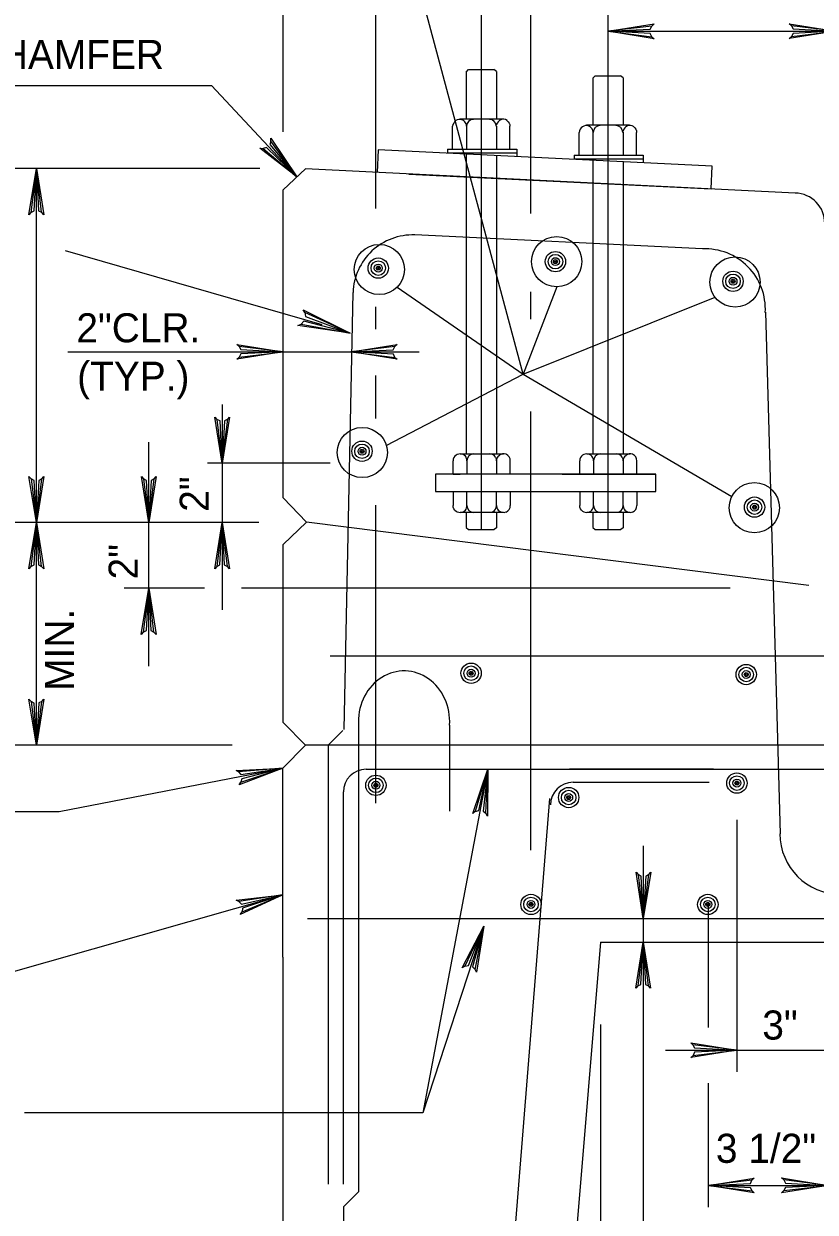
# Model space of a CAD drawing. Extents: x 642009 to 642864, y 298232 to 300014.
# Drawn here: x 642543.6 to 642625.2, y 298606.3 to 298729.1 of the extents above; entities that cross this region are included whole.
import ezdxf

# ---------------------------------------------------------------- set-up
doc = ezdxf.new("R2010")
doc.units = 0
for name, color, linetype in [('1', 7, 'Continuous'), ('10', 7, 'Continuous'), ('15', 7, 'Continuous'), ('2', 7, 'Continuous'), ('22', 7, 'Continuous'), ('3', 7, 'Continuous'), ('42', 7, 'Continuous')]:
    doc.layers.add(name, color=color, linetype=linetype)

msp = doc.modelspace()

# ---------------------------------------------------------------- linework, layer by layer
at = {"layer": '1'}
for p, q in [((642567.92, 298714.11), (642541.81, 298714.11)), ((642544.86, 298677.54), (642544.86, 298714.11)), ((642572.64, 298714.06), (642570.34, 298711.91)), ((642623.17, 298711.56), (642572.64, 298714.06)), ((642570.34, 298680.09), (642570.34, 298711.91)), ((642564.04, 298689.75), (642564.04, 298668.55)), ((642556.46, 298662.71), (642556.46, 298685.85)), ((642575.19, 298683.67), (642562.54, 298683.67)), ((642570.34, 298680.09), (642572.74, 298677.59)), ((642567.82, 298677.54), (642477.97, 298677.54)), ((642544.86, 298654.55), (642544.86, 298677.54)), ((642572.74, 298677.59), (642570.35, 298675.29)), ((642624.59, 298671.06), (642572.74, 298677.59)), ((642570.34, 298656.89), (642570.34, 298675.29)), ((642562.23, 298670.77), (642553.93, 298670.77)), ((642616.46, 298670.77), (642566.05, 298670.77)), ((642572.64, 298654.55), (642570.34, 298656.89)), ((642565.07, 298654.55), (642469.71, 298654.55)), ((642572.64, 298654.55), (642570.29, 298652.2)), ((642691.02, 298654.55), (642572.64, 298654.55)), ((642570.29, 298632.67), (642570.29, 298652.2)), ((642603.1, 298634.24), (642598.74, 298581.89)), ((642603.1, 298634.24), (642649.97, 298634.24)), ((642570.29, 298632.67), (642570.29, 298581.9))]:
    msp.add_line(p, q, dxfattribs=at)
for points in [[(642544.29, 298709.57), (642544.62, 298709.74), (642544.86, 298714.11), (642544.29, 298709.57), (642544.09, 298709.34), (642544.86, 298714.11), (642545.08, 298709.75), (642545.4, 298709.59), (642544.86, 298714.11), (642545.62, 298709.34), (642545.4, 298709.59)], [(642572.56, 298699.24), (642572.63, 298698.83), (642577.24, 298697.09), (642572.56, 298699.24), (642572.38, 298699.53), (642577.24, 298697.09), (642572.48, 298698.34), (642572.2, 298698.04), (642577.24, 298697.09), (642571.86, 298697.89), (642572.2, 298698.04)], [(642564.61, 298688.21), (642564.28, 298688.04), (642564.04, 298683.67), (642564.61, 298688.21), (642564.81, 298688.44), (642564.04, 298683.67), (642563.83, 298688.04), (642563.5, 298688.2), (642564.04, 298683.67), (642563.28, 298688.44), (642563.5, 298688.2)], [(642545.43, 298682.08), (642545.1, 298681.91), (642544.86, 298677.54), (642545.43, 298682.08), (642545.63, 298682.31), (642544.86, 298677.54), (642544.65, 298681.91), (642544.32, 298682.07), (642544.86, 298677.54), (642544.1, 298682.31), (642544.32, 298682.07)], [(642557.03, 298682.08), (642556.7, 298681.91), (642556.46, 298677.54), (642557.03, 298682.08), (642557.23, 298682.31), (642556.46, 298677.54), (642556.24, 298681.91), (642555.92, 298682.07), (642556.46, 298677.54), (642555.7, 298682.31), (642555.92, 298682.07)], [(642544.29, 298673), (642544.62, 298673.17), (642544.86, 298677.54), (642544.29, 298673), (642544.09, 298672.77), (642544.86, 298677.54), (642545.08, 298673.17), (642545.4, 298673.01), (642544.86, 298677.54), (642545.62, 298672.77), (642545.4, 298673.01)], [(642563.47, 298673), (642563.8, 298673.17), (642564.04, 298677.54), (642563.47, 298673), (642563.27, 298672.77), (642564.04, 298677.54), (642564.26, 298673.17), (642564.58, 298673.01), (642564.04, 298677.54), (642564.8, 298672.77), (642564.58, 298673.01)], [(642555.89, 298666.23), (642556.22, 298666.39), (642556.46, 298670.77), (642555.89, 298666.23), (642555.69, 298665.99), (642556.46, 298670.77), (642556.67, 298666.4), (642557, 298666.24), (642556.46, 298670.77), (642557.22, 298665.99), (642557, 298666.24)], [(642545.43, 298659.09), (642545.1, 298658.92), (642544.86, 298654.55), (642545.43, 298659.09), (642545.63, 298659.32), (642544.86, 298654.55), (642544.65, 298658.91), (642544.32, 298659.07), (642544.86, 298654.55), (642544.1, 298659.32), (642544.32, 298659.07)]]:
    msp.add_lwpolyline(points, dxfattribs=at)
msp.add_arc((642623.11, 298708.45), 3.12, 359.4063, 88.777, dxfattribs=at)
at = {"layer": '10'}
for p, q in [((642590.78, 298731.79), (642590.78, 298676.82)), ((642603.84, 298731.79), (642603.84, 298676.82))]:
    msp.add_line(p, q, dxfattribs=at)
at = {"layer": '15'}
for p, q in [((642613.6, 298705.8), (642583.91, 298707.25)), ((642577.52, 298701.3), (642576.58, 298656.18)), ((642621.66, 298645.42), (642620.13, 298699.29)), ((642626.89, 298663.74), (642575.19, 298663.74)), ((642578.11, 298657.16), (642578.11, 298608.46)), ((642574.98, 298654.55), (642576.48, 298656.08)), ((642587.51, 298656.64), (642587.51, 298647.75)), ((642574.98, 298654.55), (642574.98, 298609.24)), ((642578.89, 298652.09), (642674.18, 298652.09)), ((642614.73, 298652.09), (642599.89, 298652.09)), ((642600.26, 298650.73), (642614.3, 298650.73)), ((642576.55, 298609.24), (642576.55, 298649.74)), ((642592.98, 298588.14), (642597.85, 298649.06)), ((642572.84, 298636.68), (642678.54, 298636.68)), ((642578.11, 298608.46), (642576.55, 298606.9)), ((642576.55, 298606.9), (642576.55, 298588.15))]:
    msp.add_line(p, q, dxfattribs=at)
msp.add_lwpolyline([(642606.93, 298629.7), (642607.26, 298629.86), (642607.5, 298634.24), (642606.93, 298629.7), (642606.74, 298629.46), (642607.5, 298634.24), (642607.72, 298629.87), (642608.05, 298629.71), (642607.5, 298634.24), (642608.26, 298629.46), (642608.05, 298629.71)], dxfattribs=at)
for centre, radius, start, end in [((642583.7, 298701.09), 6.16, 88.0122, 178.0122), ((642613.88, 298699.59), 6.22, 356.8646, 92.5849), ((642578.89, 298649.74), 2.34, 90, 180), ((642600.26, 298648.39), 2.34, 90, 180), ((642627.85, 298645.42), 6.25, 180, 270)]:
    msp.add_arc(centre, radius, start, end, dxfattribs=at)
at = {"layer": '2'}
msp.add_ellipse((642582.81, 298657), major_axis=(0, 5.23), ratio=0.9, start_param=4.644026, end_param=7.865813, dxfattribs=at)
at = {"layer": '22'}
for p, q in [((642570.34, 298717.91), (642570.34, 298751.16)), ((642579.9, 298709.99), (642579.9, 298746)), ((642595.11, 298692.86), (642583, 298737.98)), ((642595.91, 298709.47), (642595.91, 298733.11)), ((642603.84, 298728.28), (642627.33, 298728.28)), ((642529.55, 298722.67), (642562.94, 298722.67)), ((642571.75, 298713.23), (642562.94, 298722.67)), ((642574.35, 298697.98), (642547.88, 298705.6)), ((642582.09, 298701.86), (642595.11, 298692.86)), ((642598.56, 298701.9), (642595.11, 298692.86)), ((642595.91, 298698.56), (642595.91, 298701.37)), ((642579.9, 298697.52), (642579.9, 298699.83)), ((642595.11, 298692.86), (642614.92, 298700.81)), ((642548.1, 298695.17), (642571.08, 298695.17)), ((642571.08, 298695.17), (642584.38, 298695.17)), ((642579.9, 298688.3), (642579.9, 298692.74)), ((642580.98, 298685.52), (642595.11, 298692.86)), ((642595.11, 298692.86), (642616.65, 298680.24)), ((642595.91, 298643.72), (642595.91, 298689.02)), ((642579.9, 298648.58), (642579.9, 298679.33)), ((642547.21, 298647.7), (642570.29, 298652.2)), ((642591.44, 298652.09), (642584.76, 298616.6)), ((642479.53, 298647.7), (642547.21, 298647.7)), ((642617.16, 298646.86), (642617.16, 298620.82)), ((642607.5, 298644.17), (642607.5, 298602.08)), ((642541.03, 298630.8), (642570.29, 298639.12)), ((642614.18, 298638.11), (642614.18, 298625.4)), ((642591.03, 298635.89), (642584.76, 298616.6)), ((642603.1, 298625.74), (642603.1, 298601.46)), ((642609.78, 298623.07), (642626.54, 298623.07)), ((642614.18, 298619.68), (642614.18, 298606.86)), ((642584.76, 298616.6), (642543.65, 298616.6)), ((642614.18, 298609.11), (642626.54, 298609.11))]:
    msp.add_line(p, q, dxfattribs=at)
for points in [[(642608.38, 298727.71), (642608.22, 298728.04), (642603.84, 298728.28), (642608.38, 298727.71), (642608.62, 298727.51), (642603.84, 298728.28), (642608.21, 298728.49), (642608.37, 298728.82), (642603.84, 298728.28), (642608.62, 298729.04), (642608.37, 298728.82)], [(642622.79, 298728.85), (642622.96, 298728.52), (642627.33, 298728.28), (642622.79, 298728.85), (642622.56, 298729.05), (642627.33, 298728.28), (642622.97, 298728.06), (642622.81, 298727.74), (642627.33, 298728.28), (642622.56, 298727.52), (642622.81, 298727.74)], [(642569.07, 298716.93), (642568.95, 298716.59), (642571.75, 298713.23), (642569.07, 298716.93), (642569.06, 298717.24), (642571.75, 298713.23), (642568.61, 298716.27), (642568.27, 298716.17), (642571.75, 298713.23), (642567.94, 298716.2), (642568.27, 298716.17)], [(642565.78, 298695.74), (642565.95, 298695.42), (642570.32, 298695.17), (642565.78, 298695.74), (642565.55, 298695.94), (642570.32, 298695.17), (642565.95, 298694.96), (642565.79, 298694.63), (642570.32, 298695.17), (642565.55, 298694.42), (642565.79, 298694.63)], [(642581.87, 298694.6), (642581.71, 298694.93), (642577.33, 298695.17), (642581.87, 298694.6), (642582.11, 298694.41), (642577.33, 298695.17), (642581.7, 298695.39), (642581.86, 298695.72), (642577.33, 298695.17), (642582.11, 298695.93), (642581.86, 298695.72)], [(642565.74, 298651.82), (642565.97, 298651.53), (642570.29, 298652.2), (642565.74, 298651.82), (642565.47, 298651.96), (642570.29, 298652.2), (642566.07, 298651.08), (642565.98, 298650.73), (642570.29, 298652.2), (642565.78, 298650.47), (642565.98, 298650.73)], [(642590.16, 298647.7), (642590.51, 298647.81), (642591.44, 298652.09), (642590.16, 298647.7), (642589.92, 298647.5), (642591.44, 298652.09), (642590.96, 298647.74), (642591.26, 298647.53), (642591.44, 298652.09), (642591.43, 298647.25), (642591.26, 298647.53)], [(642608.07, 298641.22), (642607.75, 298641.05), (642607.5, 298636.68), (642608.07, 298641.22), (642608.27, 298641.45), (642607.5, 298636.68), (642607.29, 298641.04), (642606.96, 298641.2), (642607.5, 298636.68), (642606.75, 298641.45), (642606.96, 298641.2)], [(642565.77, 298638.43), (642566.02, 298638.16), (642570.29, 298639.12), (642565.77, 298638.43), (642565.49, 298638.56), (642570.29, 298639.12), (642566.15, 298637.72), (642566.09, 298637.36), (642570.29, 298639.12), (642565.91, 298637.09), (642566.09, 298637.36)], [(642589.09, 298631.75), (642589.45, 298631.81), (642591.03, 298635.89), (642589.09, 298631.75), (642588.82, 298631.59), (642591.03, 298635.89), (642589.89, 298631.67), (642590.15, 298631.42), (642591.03, 298635.89), (642590.28, 298631.12), (642590.15, 298631.42)], [(642612.62, 298623.64), (642612.79, 298623.31), (642617.16, 298623.07), (642612.62, 298623.64), (642612.39, 298623.84), (642617.16, 298623.07), (642612.79, 298622.86), (642612.63, 298622.53), (642617.16, 298623.07), (642612.39, 298622.31), (642612.63, 298622.53)], [(642618.72, 298608.54), (642618.55, 298608.87), (642614.18, 298609.11), (642618.72, 298608.54), (642618.95, 298608.34), (642614.18, 298609.11), (642618.55, 298609.32), (642618.7, 298609.65), (642614.18, 298609.11), (642618.95, 298609.87), (642618.7, 298609.65)], [(642622, 298609.68), (642622.17, 298609.35), (642626.54, 298609.11), (642622, 298609.68), (642621.76, 298609.88), (642626.54, 298609.11), (642622.17, 298608.89), (642622.01, 298608.57), (642626.54, 298609.11), (642621.76, 298608.35), (642622.01, 298608.57)]]:
    msp.add_lwpolyline(points, dxfattribs=at)
for centre in [(642580.26, 298703.68), (642598.56, 298704.49), (642616.97, 298702.38), (642578.5, 298684.78), (642618.96, 298679.08)]:
    msp.add_circle(centre, 2.59, dxfattribs=at)
at = {"layer": '3'}
for centre, radius in [((642580.15, 298703.82), 1.05), ((642598.43, 298704.49), 1.05), ((642598.43, 298704.49), 0.75), ((642598.43, 298704.49), 0.41), ((642598.43, 298704.49), 0.207), ((642580.15, 298703.82), 0.75), ((642580.15, 298703.82), 0.41), ((642580.15, 298703.82), 0.207), ((642580.15, 298703.82), 0.0887), ((642598.43, 298704.49), 0.0887), ((642616.76, 298702.46), 1.05), ((642616.76, 298702.46), 0.75), ((642616.76, 298702.46), 0.41), ((642616.76, 298702.46), 0.207), ((642616.76, 298702.46), 0.0887), ((642578.47, 298684.91), 1.05), ((642578.47, 298684.91), 0.75), ((642578.47, 298684.91), 0.41), ((642578.47, 298684.91), 0.207), ((642578.47, 298684.91), 0.0887), ((642618.98, 298679.14), 1.05), ((642618.98, 298679.14), 0.75), ((642618.98, 298679.14), 0.41), ((642618.98, 298679.14), 0.207), ((642618.98, 298679.14), 0.0887), ((642589.73, 298661.99), 1.05), ((642589.73, 298661.99), 0.75), ((642589.73, 298661.99), 0.41), ((642589.73, 298661.99), 0.207), ((642589.73, 298661.99), 0.0887), ((642618.12, 298661.86), 1.05), ((642618.12, 298661.86), 0.75), ((642618.12, 298661.86), 0.41), ((642618.12, 298661.86), 0.207), ((642618.12, 298661.86), 0.0887), ((642579.9, 298650.42), 1.05), ((642579.9, 298650.42), 0.75), ((642579.9, 298650.42), 0.41), ((642617.16, 298650.65), 1.05), ((642617.16, 298650.65), 0.75), ((642617.16, 298650.65), 0.41), ((642617.16, 298650.65), 0.207), ((642617.16, 298650.65), 0.0887), ((642579.9, 298650.42), 0.207), ((642579.9, 298650.42), 0.0887), ((642599.8, 298649.16), 1.05), ((642599.8, 298649.16), 0.75), ((642599.8, 298649.16), 0.41), ((642599.8, 298649.16), 0.207), ((642599.8, 298649.16), 0.0887), ((642595.91, 298638.12), 1.05), ((642595.91, 298638.12), 0.75), ((642595.91, 298638.12), 0.41), ((642614.16, 298638.12), 1.05), ((642614.16, 298638.12), 0.75), ((642614.16, 298638.12), 0.41), ((642595.91, 298638.12), 0.207), ((642595.91, 298638.12), 0.0887), ((642614.16, 298638.12), 0.207), ((642614.16, 298638.12), 0.0887)]:
    msp.add_circle(centre, radius, dxfattribs=at)
at = {"layer": '42'}
for p, q in [((642589.22, 298724.07), (642589.47, 298724.32)), ((642589.47, 298724.32), (642592.09, 298724.32)), ((642592.34, 298724.11), (642592.09, 298724.32)), ((642589.22, 298724.07), (642589.22, 298719.21)), ((642592.34, 298724.11), (642592.34, 298719.21)), ((642602.28, 298723.43), (642602.53, 298723.69)), ((642602.28, 298723.43), (642602.28, 298718.57)), ((642602.53, 298723.69), (642605.15, 298723.69)), ((642605.41, 298723.47), (642605.15, 298723.69)), ((642605.41, 298723.47), (642605.41, 298718.57)), ((642587.82, 298716.12), (642587.82, 298718.47)), ((642593.03, 298719.21), (642588.56, 298719.21)), ((642589.27, 298718.47), (642589.24, 298718.7)), ((642589.24, 298718.7), (642589.24, 298716.12)), ((642592.33, 298718.47), (642592.36, 298718.64)), ((642592.36, 298718.49), (642592.36, 298716.12)), ((642593.74, 298716.12), (642593.74, 298718.47)), ((642606.09, 298718.57), (642601.63, 298718.57)), ((642600.89, 298715.48), (642600.89, 298717.83)), ((642602.33, 298717.83), (642602.3, 298718.07)), ((642602.3, 298718.07), (642602.3, 298715.48)), ((642605.39, 298717.83), (642605.42, 298718)), ((642605.42, 298717.86), (642605.42, 298715.48)), ((642606.8, 298715.48), (642606.8, 298717.83)), ((642580.13, 298716.03), (642580.02, 298713.69)), ((642614.62, 298714.35), (642580.13, 298716.03)), ((642587.29, 298716.12), (642594.44, 298716.12)), ((642587.29, 298716.12), (642587.29, 298715.73)), ((642587.29, 298715.73), (642594.44, 298715.73)), ((642594.44, 298716.11), (642594.44, 298715.34)), ((642589.22, 298715.59), (642589.22, 298684.63)), ((642592.34, 298715.44), (642592.34, 298684.63)), ((642600.35, 298715.48), (642607.5, 298715.48)), ((642600.35, 298715.48), (642600.35, 298715.09)), ((642600.35, 298715.09), (642607.5, 298715.09)), ((642602.28, 298714.95), (642602.28, 298684.63)), ((642605.41, 298714.8), (642605.41, 298684.63)), ((642607.5, 298715.48), (642607.5, 298714.7)), ((642583.31, 298713.53), (642614.5, 298712.01)), ((642614.5, 298712.01), (642614.62, 298714.35)), ((642587.89, 298682.53), (642587.89, 298683.93)), ((642588.6, 298684.63), (642593.06, 298684.63)), ((642589.3, 298683.93), (642589.3, 298682.53)), ((642592.36, 298683.93), (642592.39, 298684.16)), ((642592.36, 298683.93), (642592.36, 298682.53)), ((642592.53, 298684.4), (642592.66, 298684.5)), ((642593.77, 298682.53), (642593.77, 298683.93)), ((642600.96, 298682.53), (642600.96, 298683.93)), ((642601.66, 298684.63), (642606.13, 298684.63)), ((642602.37, 298683.93), (642602.37, 298682.53)), ((642605.42, 298683.93), (642605.46, 298684.16)), ((642605.42, 298683.93), (642605.42, 298682.53)), ((642605.59, 298684.4), (642605.72, 298684.5)), ((642606.83, 298682.53), (642606.83, 298683.93)), ((642599.12, 298682.53), (642608.79, 298682.53)), ((642587.89, 298680.74), (642587.89, 298679.31)), ((642589.3, 298679.31), (642589.3, 298680.74)), ((642592.36, 298679.31), (642592.36, 298680.74)), ((642593.77, 298680.74), (642593.77, 298679.31)), ((642599.12, 298680.74), (642608.79, 298680.74)), ((642600.96, 298680.74), (642600.96, 298679.31)), ((642602.37, 298679.31), (642602.37, 298680.74)), ((642605.42, 298679.31), (642605.42, 298680.74)), ((642606.83, 298680.74), (642606.83, 298679.31)), ((642592.36, 298679.31), (642592.39, 298679.08)), ((642605.42, 298679.31), (642605.46, 298679.08)), ((642588.6, 298678.61), (642593.06, 298678.61)), ((642589.22, 298678.61), (642589.22, 298677.05)), ((642592.34, 298678.61), (642592.34, 298677.02)), ((642592.53, 298678.84), (642592.66, 298678.74)), ((642601.66, 298678.61), (642606.13, 298678.61)), ((642602.28, 298678.61), (642602.28, 298677.05)), ((642605.41, 298678.61), (642605.41, 298677.02)), ((642605.59, 298678.84), (642605.72, 298678.74)), ((642589.22, 298677.05), (642589.45, 298676.82)), ((642589.45, 298676.82), (642592.11, 298676.82)), ((642592.34, 298677.02), (642592.11, 298676.82)), ((642602.28, 298677.05), (642602.52, 298676.82)), ((642602.52, 298676.82), (642605.17, 298676.82)), ((642605.41, 298677.02), (642605.17, 298676.82))]:
    msp.add_line(p, q, dxfattribs=at)
for points in [[(642588.03, 298718.94), (642587.93, 298718.8), (642587.86, 298718.64), (642587.82, 298718.47)], [(642593.43, 298719.07), (642593.57, 298718.94), (642593.67, 298718.8), (642593.74, 298718.64), (642593.74, 298718.47)], [(642601.09, 298718.3), (642600.99, 298718.17), (642600.92, 298718), (642600.89, 298717.83)], [(642606.5, 298718.44), (642606.63, 298718.3), (642606.73, 298718.17), (642606.8, 298718), (642606.8, 298717.83)], [(642588.06, 298684.4), (642587.96, 298684.26), (642587.89, 298684.1), (642587.89, 298683.93)], [(642592.26, 298684.3), (642592.33, 298684.13), (642592.36, 298683.93)], [(642601.12, 298684.4), (642601.02, 298684.26), (642600.96, 298684.1), (642600.96, 298683.93)], [(642605.32, 298684.3), (642605.39, 298684.13), (642605.42, 298683.93)], [(642593.77, 298682.53), (642587.89, 298682.53), (642588.6, 298682.53)], [(642606.83, 298682.53), (642600.96, 298682.53), (642601.66, 298682.53)], [(642588.06, 298678.84), (642587.96, 298678.98), (642587.89, 298679.15), (642587.89, 298679.31)], [(642592.26, 298678.94), (642592.33, 298679.11), (642592.36, 298679.31)], [(642601.12, 298678.84), (642601.02, 298678.98), (642600.96, 298679.15), (642600.96, 298679.31)], [(642605.32, 298678.94), (642605.39, 298679.11), (642605.42, 298679.31)]]:
    msp.add_lwpolyline(points, dxfattribs=at)
msp.add_lwpolyline([(642586.06, 298680.74), (642608.79, 298680.74), (642608.79, 298682.53), (642586.06, 298682.53)], close=True, dxfattribs=at)
for centre, radius, start, end in [((642588.55, 298718.48), 0.699, 83.6098, 138.8912), ((642588.54, 298718.48), 0.7, 40.9585, 82.44), ((642588.55, 298718.44), 0.722, 2.4578, 43.9393), ((642589.97, 298718.47), 0.705, 90.005, 180.003), ((642591.62, 298718.47), 0.705, 0.001, 89.999), ((642593.06, 298718.47), 0.716, 111.3369, 166.8343), ((642593.05, 298718.5), 0.692, 56.3503, 111.6317), ((642601.62, 298717.84), 0.699, 83.6098, 138.8912), ((642601.6, 298717.84), 0.7, 40.9585, 82.44), ((642601.61, 298717.8), 0.722, 2.4578, 43.9393), ((642603.04, 298717.83), 0.705, 90.005, 180.003), ((642604.68, 298717.83), 0.705, 0.001, 89.999), ((642606.12, 298717.84), 0.716, 111.3369, 166.8343), ((642606.11, 298717.86), 0.692, 56.3503, 111.6317), ((642588.6, 298683.92), 0.718, 41.5445, 138.4555), ((642588.6, 298683.94), 0.705, 358.9131, 40.3946), ((642590.01, 298683.93), 0.705, 90.002, 179.999), ((642591.66, 298683.94), 0.691, 30.94, 90.9508), ((642593.06, 298683.94), 0.705, 139.6054, 181.0869), ((642593.09, 298683.91), 0.729, 70.7821, 126.2795), ((642593.07, 298683.95), 0.704, 358.368, 67.6797), ((642601.66, 298683.92), 0.718, 41.5445, 138.4555), ((642601.66, 298683.94), 0.705, 358.9131, 40.3946), ((642603.07, 298683.93), 0.705, 90.002, 179.999), ((642604.73, 298683.94), 0.691, 30.94, 90.9508), ((642606.13, 298683.94), 0.705, 139.6054, 181.0869), ((642606.16, 298683.91), 0.729, 70.7821, 126.2795), ((642606.13, 298683.95), 0.704, 358.368, 67.6797), ((642588.6, 298679.3), 0.705, 319.6054, 1.0869), ((642590.01, 298679.31), 0.705, 180.001, 269.998), ((642591.66, 298679.3), 0.691, 269.0492, 329.06), ((642593.06, 298679.3), 0.705, 178.9131, 220.3946), ((642593.07, 298679.29), 0.704, 292.3203, 1.632), ((642601.66, 298679.3), 0.705, 319.6054, 1.0869), ((642603.07, 298679.31), 0.705, 180.001, 269.998), ((642604.73, 298679.3), 0.691, 269.0492, 329.06), ((642606.13, 298679.3), 0.705, 178.9131, 220.3946), ((642606.13, 298679.29), 0.704, 292.3203, 1.632), ((642588.6, 298679.32), 0.718, 221.5445, 318.4555), ((642593.09, 298679.33), 0.729, 233.7205, 289.2179), ((642601.66, 298679.32), 0.718, 221.5445, 318.4555), ((642606.16, 298679.33), 0.729, 233.7205, 289.2179)]:
    msp.add_arc(centre, radius, start, end, dxfattribs=at)

# ---------------------------------------------------------------- texts
at = {"layer": '1'}
for s, p in [('2"', (642562.66, 298678.66)), ('2"', (642555.32, 298671.68)), ('MIN.', (642548.74, 298660.18))]:
    msp.add_text(s, height=3, rotation=90, dxfattribs=at).set_placement(p)
at = {"layer": '22'}
msp.add_text('3/4" CHAMFER', height=2.9997, rotation=360, dxfattribs=at).set_placement((642530.09, 298724.38))
for s, p in [('2"CLR.', (642548.99, 298696.16)), ('(TYP.)', (642549.07, 298691.16)), ('3"', (642619.78, 298624.17)), ('3 1/2"', (642614.99, 298611.44))]:
    msp.add_text(s, height=3, dxfattribs=at).set_placement(p)

doc.saveas('drawing.dxf')
